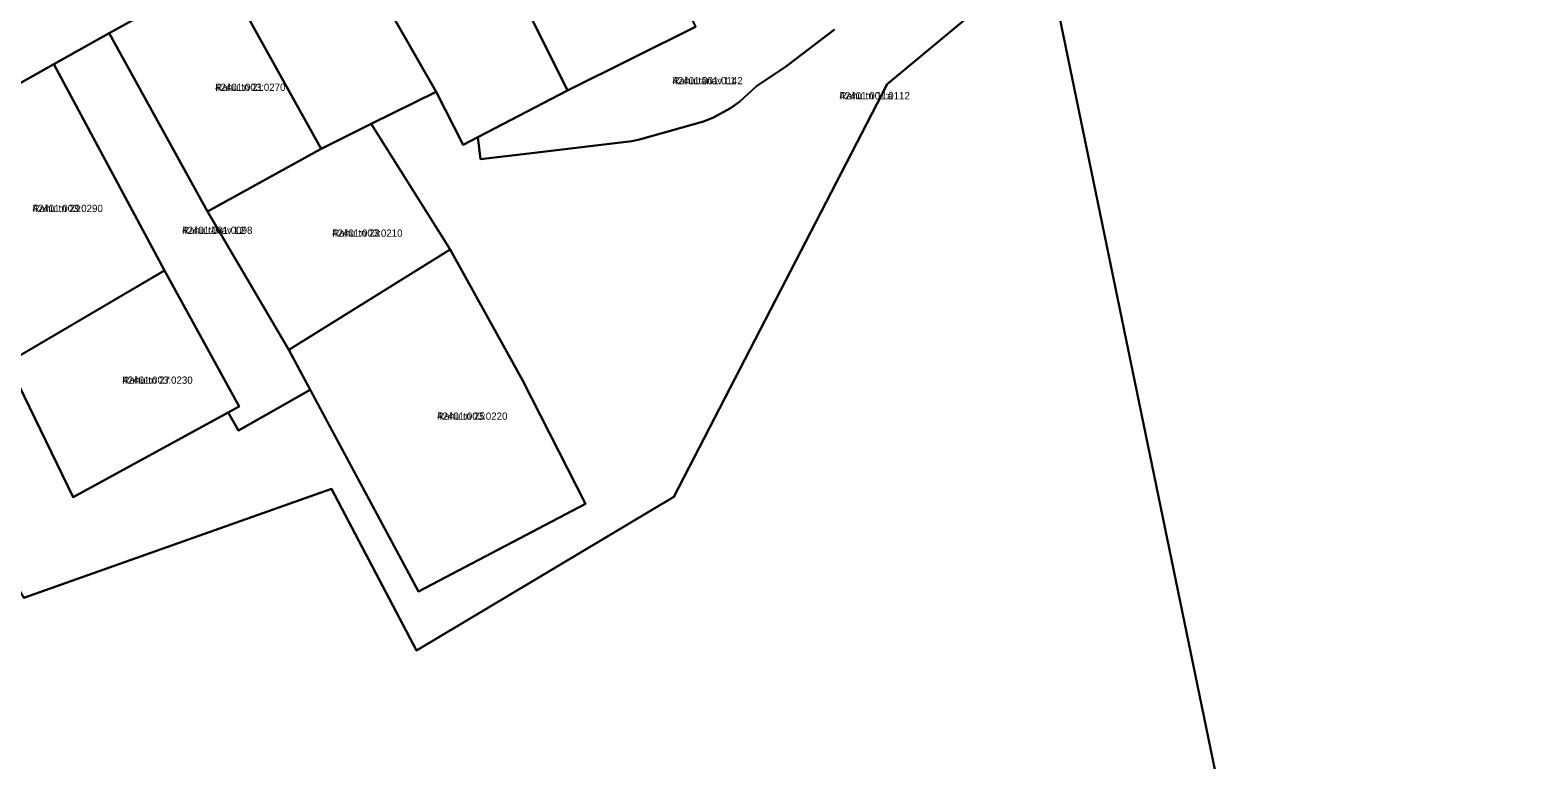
# Model space of a CAD drawing. Extents: x 595979 to 597983, y 6604231 to 6607350.
# Drawn here: x 596865.4 to 597176.2, y 6605070.1 to 6605220.6 of the extents above; entities that cross this region are included whole.
import ezdxf

# ---------------------------------------------------------------- set-up
doc = ezdxf.new("R2010")
doc.units = 0
for name, color, linetype in [('L_AADRESS', 7, 'Continuous'), ('PIIR', 7, 'Continuous'), ('TUNNUS', 7, 'Continuous')]:
    doc.layers.add(name, color=color, linetype=linetype)

msp = doc.modelspace()

# ---------------------------------------------------------------- linework, layer by layer
at = {"layer": 'PIIR'}
for points in [[(597191.72, 6605387.01), (597156.63, 6605368.74), (597130.33, 6605354.15), (597103, 6605339.04), (597076.68, 6605324.49), (597050.42, 6605309.97), (597024.14, 6605295.52), (597016.87, 6605291.63), (597005.04, 6605285.24), (596978.08, 6605271.56), (596951.16, 6605258.14), (596927.39, 6605245.75), (596904.92, 6605232.87), (596881.66, 6605219.93), (596870.26, 6605213.58), (596838.64, 6605195.76), (596802.93, 6605177.68), (596776.88, 6605161.66), (596775.35, 6605164.36), (596751.28, 6605150.91), (596753, 6605147.82), (596739.75, 6605141.48), (596618.18, 6605072.86), (596613.27, 6605068.86)], [(597211.99, 6605298.86), (597070.11, 6605259.35), (597074.78, 6605236.74), (597042, 6605209.45), (596998.07, 6605124.37), (596944.97, 6605092.68), (596927.46, 6605126.04), (596864.06, 6605103.52)], [(597031.15, 6605220.71), (597021.59, 6605213.4), (597021.1, 6605213.04), (597015.09, 6605209), (597011.66, 6605205.88), (597009.75, 6605204.52), (597006.26, 6605202.6), (597004.17, 6605201.74), (596990.95, 6605198.01), (596989.41, 6605197.7), (596968.15, 6605195.17), (596958.22, 6605193.99), (596957.67, 6605198.54), (596976.15, 6605208.15), (597002.49, 6605221.28)], [(596860.75, 6605152.06), (596874.19, 6605124.28), (596906.17, 6605141.77), (596908.3, 6605138.02), (596923.1, 6605146.42), (596945.43, 6605104.81), (596979.85, 6605122.91), (596966.83, 6605148.44), (596951.91, 6605175.33), (596935.66, 6605201.28), (596949.09, 6605207.85), (596954.65, 6605196.96), (596957.67, 6605198.54), (596958.22, 6605193.99), (596968.15, 6605195.17), (596989.41, 6605197.7), (596990.95, 6605198.01), (597004.17, 6605201.74), (597006.26, 6605202.6), (597009.75, 6605204.52), (597011.66, 6605205.88), (597015.09, 6605209), (597021.1, 6605213.04), (597021.59, 6605213.4), (597031.15, 6605220.71)]]:
    msp.add_lwpolyline(points, dxfattribs=at)
for points in [[(597070.11, 6605259.35), (597211.99, 6605298.86), (597260.5, 6605224.72), (597285.2, 6605184.34), (597299.38, 6605162.18), (597321.75, 6605127.1), (597316.32, 6605100.66), (597302.35, 6605090.93), (597218.27, 6605028.59), (597130.93, 6604964.61), (597074.78, 6605236.74)], [(596968.96, 6605222.53), (596951.16, 6605258.14), (596978.08, 6605271.56), (596995.57, 6605235.53), (597002.49, 6605221.28), (596976.15, 6605208.15)], [(596949.09, 6605207.85), (596927.39, 6605245.75), (596951.16, 6605258.14), (596968.96, 6605222.53), (596976.15, 6605208.15), (596957.67, 6605198.54), (596954.65, 6605196.96)], [(596927.39, 6605245.75), (596949.09, 6605207.85), (596935.66, 6605201.28), (596925.33, 6605196.14), (596904.92, 6605232.87)], [(597074.78, 6605236.74), (597130.93, 6604964.61), (596884.36, 6604783.54), (596826.22, 6604842.59), (596722.52, 6604944.87), (596673.89, 6604997.16), (596676.44, 6605002.97), (596651.51, 6605028.71), (596644.52, 6605036.02), (596772.01, 6605113.71), (596777.85, 6605097.85), (596847.38, 6605131.33), (596864.06, 6605103.52), (596927.46, 6605126.04), (596944.97, 6605092.68), (596998.07, 6605124.37), (597042, 6605209.45)], [(596904.92, 6605232.87), (596925.33, 6605196.14), (596901.94, 6605183.19), (596881.66, 6605219.93)], [(596923.1, 6605146.42), (596908.3, 6605138.02), (596906.17, 6605141.77), (596908.41, 6605142.99), (596893.05, 6605171.06), (596870.26, 6605213.58), (596881.66, 6605219.93), (596901.94, 6605183.19), (596918.66, 6605154.69)], [(596870.26, 6605213.58), (596893.05, 6605171.06), (596858.43, 6605150.7), (596838.64, 6605195.76)], [(596901.94, 6605183.19), (596925.33, 6605196.14), (596935.66, 6605201.28), (596951.91, 6605175.33), (596918.66, 6605154.69)], [(596951.91, 6605175.33), (596966.83, 6605148.44), (596979.85, 6605122.91), (596945.43, 6605104.81), (596918.66, 6605154.69)], [(596893.05, 6605171.06), (596908.41, 6605142.99), (596906.17, 6605141.77), (596874.19, 6605124.28), (596860.75, 6605152.06)]]:
    msp.add_lwpolyline(points, close=True, dxfattribs=at)

# ---------------------------------------------------------------- texts
at = {"layer": 'L_AADRESS'}
for s, p in [('Rahu tn 21', (596903.49, 6605208.06)), ('Rahu tänav L1', (596997.75, 6605209.42)), ('Rahu tn 11a', (597032.21, 6605206.31)), ('Rahu tn 29', (596865.84, 6605183.08)), ('Rahu tänav L2', (596896.68, 6605178.57)), ('Rahu tn 23', (596927.62, 6605177.99)), ('Rahu tn 27', (596884.36, 6605147.67)), ('Rahu tn 25', (596949.25, 6605140.25))]:
    msp.add_text(s, height=1.5, dxfattribs=at).set_placement(p)
at = {"layer": 'TUNNUS'}
for s, p in [('42401:003:0270', (596903.49, 6605208.06)), ('42401:001:0142', (596997.75, 6605209.42)), ('42401:001:0112', (597032.21, 6605206.31)), ('42401:003:0290', (596865.84, 6605183.08)), ('42401:001:0098', (596896.68, 6605178.57)), ('42401:003:0210', (596927.62, 6605177.99)), ('42401:003:0230', (596884.36, 6605147.67)), ('42401:003:0220', (596949.25, 6605140.25))]:
    msp.add_text(s, height=1.5, dxfattribs=at).set_placement(p)

doc.saveas('drawing.dxf')
